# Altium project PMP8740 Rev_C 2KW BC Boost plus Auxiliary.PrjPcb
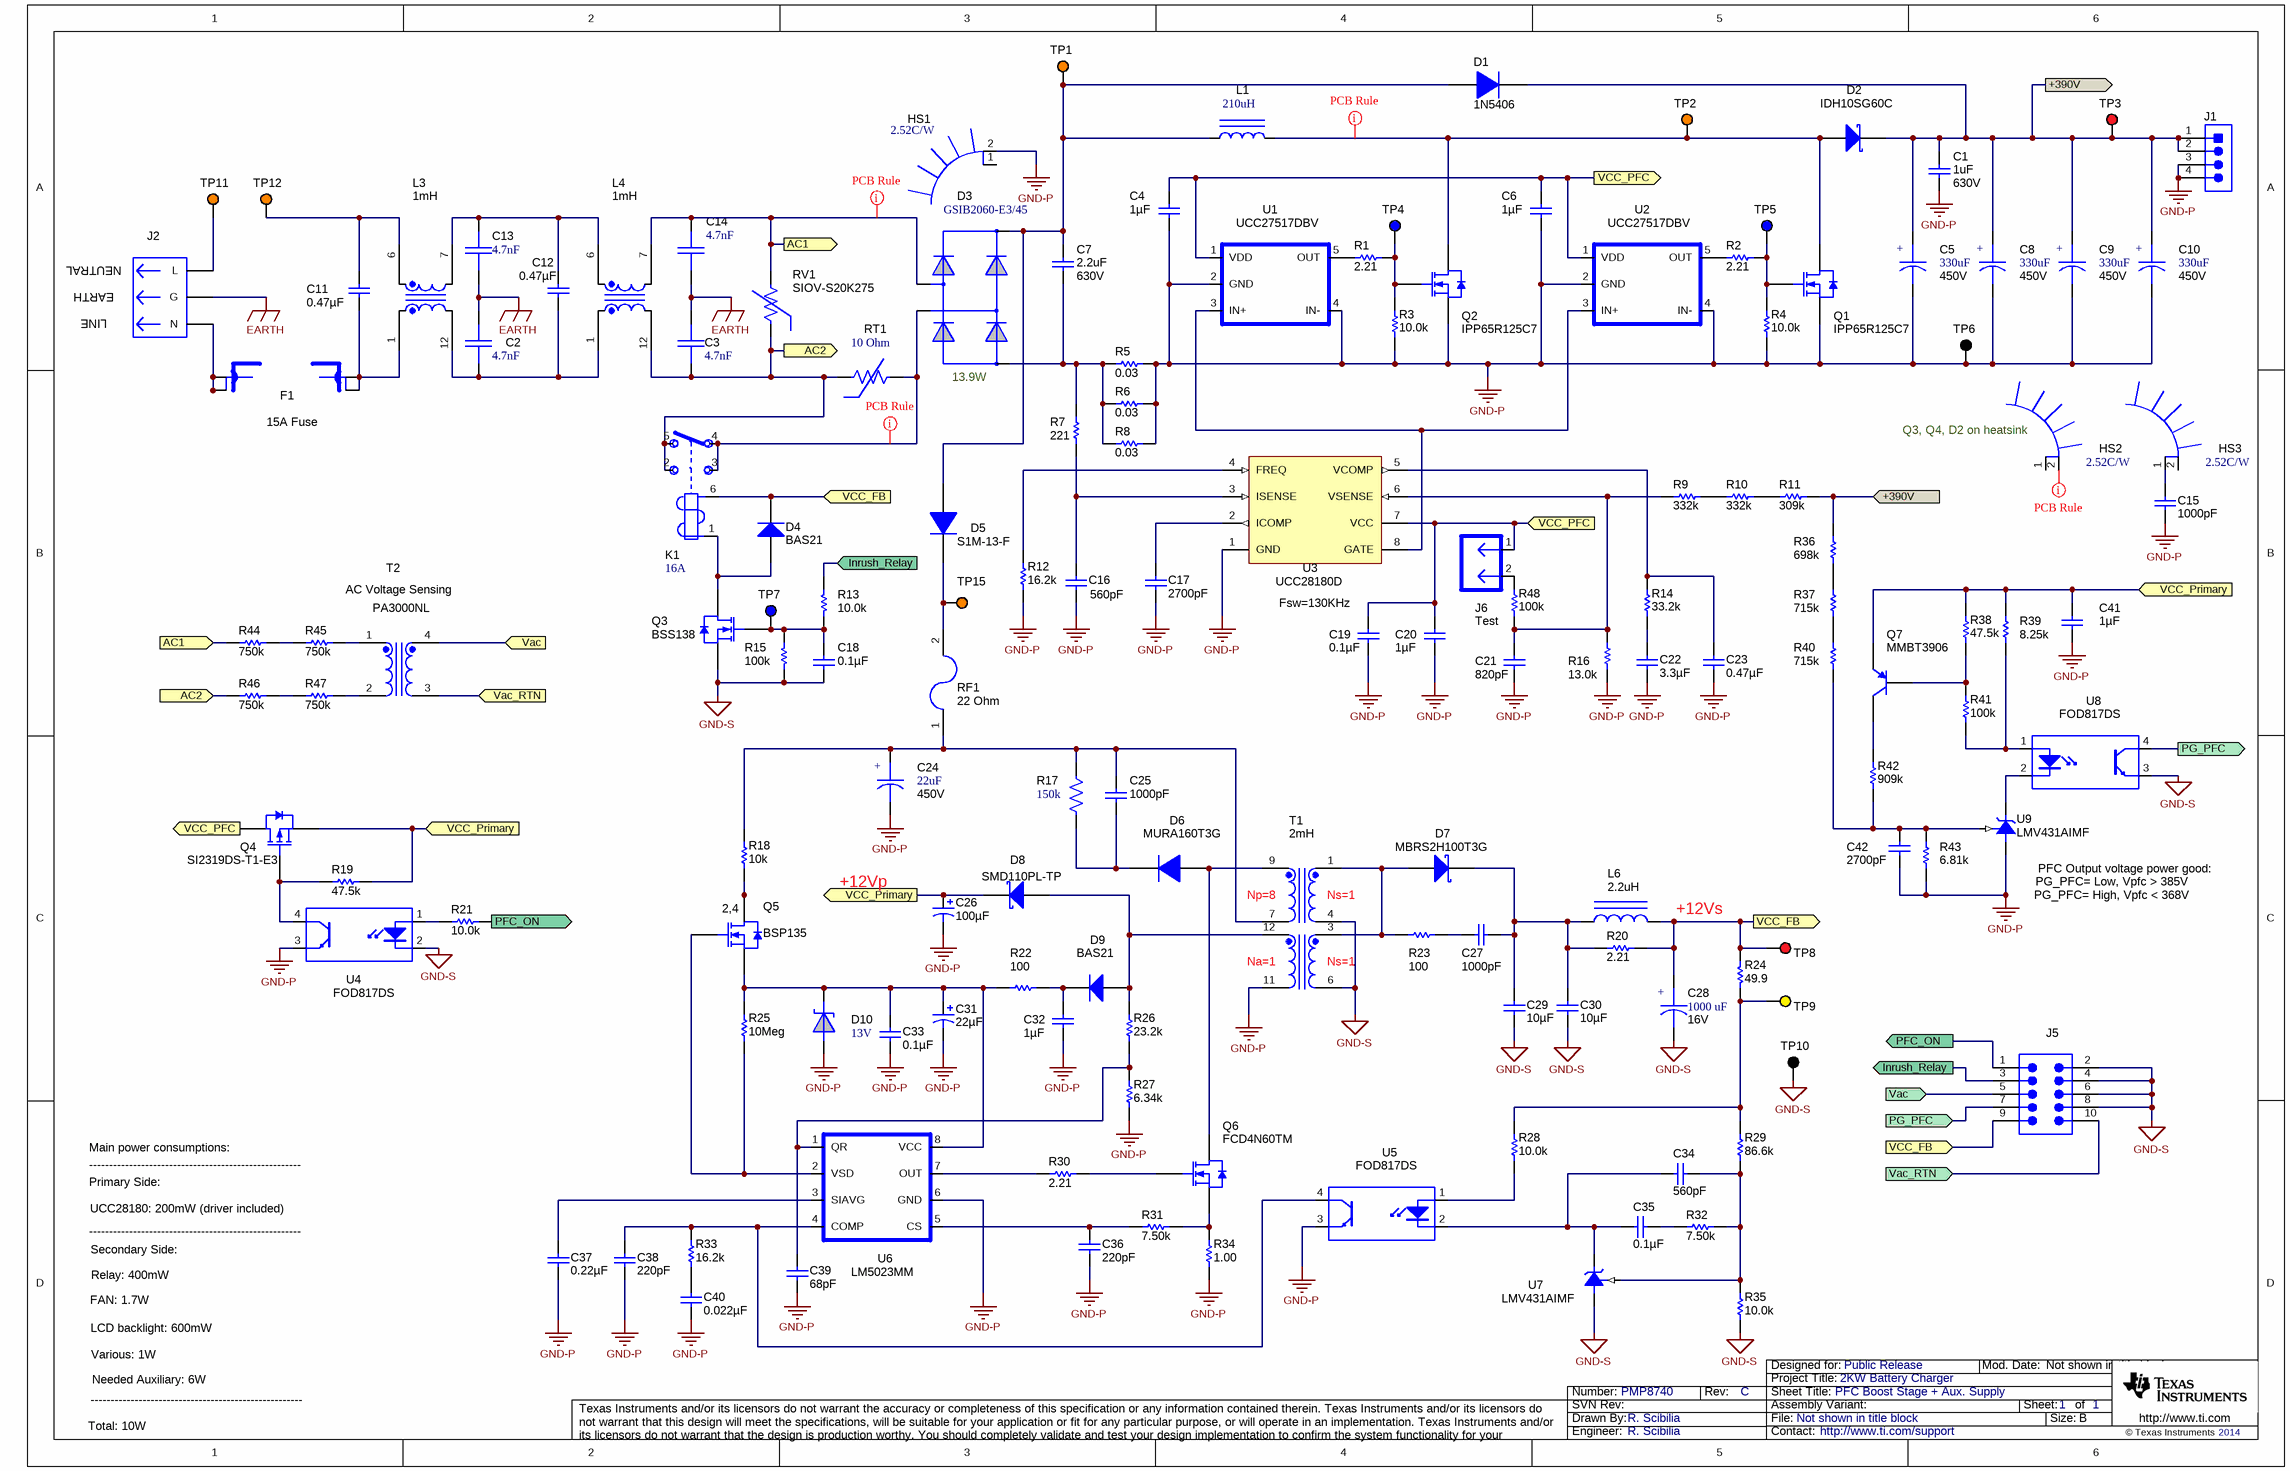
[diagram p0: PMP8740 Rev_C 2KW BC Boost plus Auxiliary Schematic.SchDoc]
CopyrightYear: 2014; PCB_Layout: R. Scibilia; PCB_Rev: C; PRJ_Customer: Public Release; PRJ_Engineer: R. Scibilia; PRJ_Number: PMP8740; PRJ_Title: 2KW Battery Charger; SCH_Rev: C; TechSupport: http://www.ti.com/support
1 sheet, 147 parts. Net scope: flat (ports and power ports of the same name join across sheets).
Board file: PMP8740 Rev_C 2KW BC Boost plus Auxiliary Board.PcbDoc

## Sheet PMP8740 Rev_C 2KW BC Boost plus Auxiliary Schematic.SchDoc: PFC Boost Stage + Aux. Supply
size 431 x 279 mm; Date: Not shown in title block; ApprovedBy: Not shown in title block; CheckedBy: Not shown in title block; Author: Not shown in title block; CompanyName: Not shown in title block; DrawnBy: R. Scibilia; Engineer: Not shown in title block; Organization: Not shown in title block; Address1: Not shown in title block; Address2: Not shown in title block; Address3: Not shown in title block; Address4: Not shown in title block; DocumentNumber: 1; Revision: Use project parameter SCH_Rev; SheetNumber: 1; SheetTotal: 1; PageSetup: Record=PageOptions|CenterHorizontal=True|CenterVertical=True|PrintScale=1.00|XCorrection=1.00|YCorrection=1.00|PrintKind=0|BorderSize=5000000|LeftOffset=0|BottomOffset=0|Orientation=2|PaperLength=1000|PaperWidth=1000|Scale=100|PaperSource=15|PrintQuality=600|MediaType=1|DitherType=10|PaperKind=Letter|PrintScaleMode=1

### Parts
C1  value 1uF  VDC_V: 630V  [B32924_21.5mm]  (hidden comment: R75PR4100AA30K)
C2  value 4.7nF  [CAP_LEAD_394]  (hidden comment: C961U472MYWDBA7317)
C3  value 4.7nF  [CAP_LEAD_394]  (hidden comment: C961U472MYWDBA7317)
C4  ValueDisplayed: 1µF  [0603]  (hidden comment: C1608X7R1E105K080AB)
C5  value 330uF  Voltage: 450V  [CAP_381L_35MM]  (hidden comment: EET-ED2W331EA)
C6  ValueDisplayed: 1µF  [0603]  (hidden comment: C1608X7R1E105K080AB)
C7  value 2.2uF  Value2: 630V  [B32923_29.5mm]  (hidden comment: ECW-FA2J225J)
C8  value 330uF  Voltage: 450V  [CAP_381L_35MM]  (hidden comment: EET-ED2W331EA)
C9  value 330uF  Voltage: 450V  [CAP_381L_35MM]  (hidden comment: EET-ED2W331EA)
C10  value 330uF  Voltage: 450V  [CAP_381L_35MM]  (hidden comment: EET-ED2W331EA)
C11  ValueDisplayed: 0.47µF  [CAPRR2250W80L2550T850H1750]  (hidden comment: ECQ-U2A474ML)
C12  ValueDisplayed: 0.47µF  [CAPRR2250W80L2550T850H1750]  (hidden comment: ECQ-U2A474ML)
C13  value 4.7nF  [CAP_LEAD_394]  (hidden comment: C961U472MYWDBA7317)
C14  value 4.7nF  [CAP_LEAD_394]  (hidden comment: C961U472MYWDBA7317)
C15  ValueDisplayed: 1000pF  [1206]  (hidden comment: CC1206KKX7RCBB102)
C16  ValueDisplayed: 560pF  [0603]  (hidden comment: C1608C0G1H561J)
C17  ValueDisplayed: 2700pF  [0603]  (hidden comment: C1608C0G1H272J)
C18  ValueDisplayed: 0.1µF  [0603]  (hidden comment: C1608X7R1H104K)
C19  ValueDisplayed: 0.1µF  [0603]  (hidden comment: C1608X7R1H104K)
C20  ValueDisplayed: 1µF  [0603]  (hidden comment: C1608X7R1E105K080AB)
C21  ValueDisplayed: 820pF  [0603]  (hidden comment: C1608C0G1H821J)
C22  ValueDisplayed: 3.3µF  [1206]  (hidden comment: GRM31CR71C335KA01L)
C23  ValueDisplayed: 0.47µF  [0603]  (hidden comment: C1608X5R1A474K)
C24  value 22uF  Voltage: 450V  [CAP_ZL-7.5X14.5MM]  (hidden comment: EKXG451ELL220ML20S)
C25  ValueDisplayed: 1000pF  [0805_HV]  (hidden comment: C2012X7R2E102K)
C26  ValueDisplayed: 100µF  [SM_RADIAL_E]  (hidden comment: EEE-FK1E101P)
C27  ValueDisplayed: 1000pF  [0805_HV]  (hidden comment: C2012X7R2E102K)
C28  value 1000 uF  Voltage: 16V  [CAP_ALUM-10MM]  (hidden comment: UHM1C102MPD)
C29  ValueDisplayed: 10µF  [1210]  (hidden comment: C3225X7R1E106M)
C30  ValueDisplayed: 10µF  [1210]  (hidden comment: C3225X7R1E106M)
C31  ValueDisplayed: 22µF  [SM_RADIAL_D]  (hidden comment: EEE-FK1H220P)
C32  ValueDisplayed: 1µF  [0603]  (hidden comment: C1608X7R1E105K080AB)
C33  ValueDisplayed: 0.1µF  [0603]  (hidden comment: C1608X7R1H104K)
C34  ValueDisplayed: 560pF  [0603]  (hidden comment: C1608C0G1H561J)
C35  ValueDisplayed: 0.1µF  [0603]  (hidden comment: C1608X7R1H104K)
C36  ValueDisplayed: 220pF  [0603]  (hidden comment: C1608C0G1H221J)
C37  ValueDisplayed: 0.22µF  [0603]  (hidden comment: C1608X7R1C224K)
C38  ValueDisplayed: 220pF  [0603]  (hidden comment: C1608C0G1H221J)
C39  ValueDisplayed: 68pF  [0603]  (hidden comment: C1608C0G1H680J)
C40  ValueDisplayed: 0.022µF  [0603]  (hidden comment: C1608X7R2A223K)
C41  ValueDisplayed: 1µF  [0603]  (hidden comment: C1608X7R1E105K080AB)
C42  ValueDisplayed: 2700pF  [0603]  (hidden comment: C1608C0G1H272J)
D1  1N5406  [DO-201AD]
D2  IDH10SG60C  [TO-220-2]
D3  value GSIB2060-E3/45  [BRIDGE-TSIL_PKG]  (hidden comment: D-BRIDGE_GSIB_20A_SERIES)
D4  value BAS21  [SOT-23]  (hidden comment: BAS21-7-F)
D5  S1M-13-F  [SMA]
D6  MURA160T3G  [SMA]
D7  MBRS2H100T3G  [SMB]
D8  SMD110PL-TP  [SOD-123FL]
D9  value BAS21  [SOT-23]  (hidden comment: BAS21-7-F)
D10  value 13V  [SOD-323]  (hidden comment: D-MMSZ52XXBS_SERIES)
F1  15A Fuse  [FUSE_HOLDER_1/4]
HS1  value 2.52C/W  [HEATSINK_780603B0200]  (hidden comment: HEATSINK_780603B0200)
HS2  value 2.52C/W  [HEATSINK_780603B0200]  (hidden comment: HEATSINK_780603B0200)
HS3  value 2.52C/W  [HEATSINK_780603B0200]  (hidden comment: HEATSINK_780603B0200)
J1  0015244557  [CONN_0015244557]  (value not drawn)
J2  703W-00/54  [CONN_QUALTEK-703W-0054]  (value not drawn)
J5  5103308-1  [CONN_5103308-1]  (value not drawn)
J6  Test  [HDR100_1X2]
K1  value 16A  [RELAY_ALZ_FORM_A]  (hidden comment: ALZ51B12)
L1  value 210uH  [IND_TOR_1600MIL]  (hidden comment: 170.804 (SDR 15,0-0,21))
L3  value 1mH  [WE-CMB_XL]  (hidden comment: 744825510)
L4  value 1mH  [WE-CMB_XL]  (hidden comment: 744825510)
L6  value 2.2uH  [WE-PD2-MS]  (hidden comment: 7447745022)
Q1  IPP65R125C7  [TO-220AB]
Q2  IPP65R125C7  [TO-220AB]
Q3  BSS138  [SOT-23]
Q4  SI2319DS-T1-E3  [SOT-23]
Q5  BSP135  [SOT-223]
Q6  FCD4N60TM  [DPAK]
Q7  MMBT3906  [SOT-23]
R1  value 2.21  [0805_HV]  (hidden comment: CRCW08052R21FKEA)
R2  value 2.21  [0805_HV]  (hidden comment: CRCW08052R21FKEA)
R3  value 10.0k  [0603]  (hidden comment: CRCW060310K0FKEA)
R4  value 10.0k  [0603]  (hidden comment: CRCW060310K0FKEA)
R5  value 0.03  [2512]  (hidden comment: CSRN2512FK30L0)
R6  value 0.03  [2512]  (hidden comment: CSRN2512FK30L0)
R7  value 221  [0603]  (hidden comment: CRCW0603221RFKEA)
R8  value 0.03  [2512]  (hidden comment: CSRN2512FK30L0)
R9  value 332k  [1206]  (hidden comment: CRCW1206332KFKEA)
R10  value 332k  [1206]  (hidden comment: CRCW1206332KFKEA)
R11  value 309k  [1206]  (hidden comment: CRCW1206309KFKEA)
R12  value 16.2k  [0603]  (hidden comment: CRCW060316K2FKEA)
R13  value 10.0k  [0603]  (hidden comment: CRCW060310K0FKEA)
R14  value 33.2k  [0603]  (hidden comment: CRCW060333K2FKEA)
R15  value 100k  [0603]  (hidden comment: CRCW0603100KFKEA)
R16  value 13.0k  [0603]  (hidden comment: CRCW060313K0FKEA)
R17  value 150k  [R2010]  (hidden comment: STD)
R18  value 10k  [2512M]  (hidden comment: CRCW251210K0FKEGHP)
R19  value 47.5k  [0603]  (hidden comment: CRCW060347K5FKEA)
R20  value 2.21  [0805_HV]  (hidden comment: CRCW08052R21FKEA)
R21  value 10.0k  [0603]  (hidden comment: CRCW060310K0FKEA)
R22  value 100  [1206]  (hidden comment: CRCW1206100RFKEA)
R23  value 100  [1206]  (hidden comment: CRCW1206100RFKEA)
R24  value 49.9  [0603]  (hidden comment: CRCW060349R9FKEA)
R25  value 10Meg  [1206]  (hidden comment: CRCW120610M0JNEA)
R26  value 23.2k  [0603]  (hidden comment: CRCW060323K2FKEA)
R27  value 6.34k  [0603]  (hidden comment: CRCW06036K34FKEA)
R28  value 10.0k  [0603]  (hidden comment: CRCW060310K0FKEA)
R29  value 86.6k  [0603]  (hidden comment: CRCW060386K6FKEA)
R30  value 2.21  [0805_HV]  (hidden comment: CRCW08052R21FKEA)
R31  value 7.50k  [0603]  (hidden comment: CRCW06037K50FKEA)
R32  value 7.50k  [0603]  (hidden comment: CRCW06037K50FKEA)
R33  value 16.2k  [0603]  (hidden comment: CRCW060316K2FKEA)
R34  value 1.00  [1206]  (hidden comment: CRCW12061R00FKEA)
R35  value 10.0k  [0603]  (hidden comment: CRCW060310K0FKEA)
R36  value 698k  [1206]  (hidden comment: CRCW1206698KFKEA)
R37  value 715k  [1206]  (hidden comment: CRCW1206715KFKEA)
R38  value 47.5k  [0603]  (hidden comment: CRCW060347K5FKEA)
R39  value 8.25k  [0603]  (hidden comment: CRCW06038K25FKEA)
R40  value 715k  [1206]  (hidden comment: CRCW1206715KFKEA)
R41  value 100k  [0603]  (hidden comment: CRCW0603100KFKEA)
R42  value 909k  [0603]  (hidden comment: CRCW0603909KFKEA)
R43  value 6.81k  [0603]  (hidden comment: CRCW06036K81FKEA)
R44  value 750k  [1206]  (hidden comment: CRCW1206750KFKEA)
R45  value 750k  [1206]  (hidden comment: CRCW1206750KFKEA)
R46  value 750k  [1206]  (hidden comment: CRCW1206750KFKEA)
R47  value 750k  [1206]  (hidden comment: CRCW1206750KFKEA)
R48  value 100k  [0603]  (hidden comment: CRCW0603100KFKEA)
RF1  value 22 Ohm  [EMC2]  (hidden comment: EMC2-22RKI)
RT1  value 10 Ohm  [DISK-7X21MM]  (hidden comment: B57464S100M)
RV1  SIOV-S20K275  [DISK-846]
T1  value 2mH  [Wurth_760871113]  (hidden comment: TBD)
T2  PA3000NL  [PULSE_PA3000NL]
TP1  5008  [Keystone5008]  (value not drawn)
TP2  5008  [Keystone5008]  (value not drawn)
TP3  5005  [Keystone5005]  (value not drawn)
TP4  5122  [Keystone5122]  (value not drawn)
TP5  5122  [Keystone5122]  (value not drawn)
TP6  5006  [Keystone5006]  (value not drawn)
TP7  5122  [Keystone5122]  (value not drawn)
TP8  5000  [Keystone5000]  (value not drawn)
TP9  5004  [Keystone5004]  (value not drawn)
TP10  5001  [Keystone5001]  (value not drawn)
TP11  5008  [Keystone5008]  (value not drawn)
TP12  5008  [Keystone5008]  (value not drawn)
TP15  5008  [Keystone5008]  (value not drawn)
U1  UCC27517DBV  [SOT23-5P]
U2  UCC27517DBV  [SOT23-5P]
U3  UCC28180D  [D0008A_N]
U4  FOD817DS  [N04C]
U5  FOD817DS  [N04C]
U6  LM5023MM  [DGK8]
U7  LMV431AIMF  [MF03A_N]
U8  FOD817DS  [N04C]
U9  LMV431AIMF  [MF03A_N]

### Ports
+390V, AC1, AC2, Inrush_Relay, PFC_ON, PG_PFC, Vac, Vac_RTN, VCC_FB, VCC_PFC, VCC_Primary

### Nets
EARTH: C2.1 C3.1 C13.2 C14.2 J2.3(G)
GND-P: C1.2 C4.2 C5.2 C6.2 C8.2 C9.2 C10.2 C15.2 C16.2 C17.2 C19.2 C20.2 C21.2 C22.2 C23.2 C24.2 C26.2(-) C31.2(-) C32.2 C33.1 C36.2 C37.2 C38.2 C39.2 C40.2 C41.2 C42.2 D10.2(A) HS1.2 J1.3 J1.4 Q1.3(S) Q2.3(S) R3.1 R4.1 R5.2 R6.2 R8.2 R12.1 R16.1 R27.1 R34.1 R43.1 T1.11 TP6.1 U1.2(GND) U1.4(IN-) U2.2(GND) U2.4(IN-) U3.1(GND) U4.3(E) U5.3(E) U6.6(GND) U9.3(A)
GND-S: C18.1 C28.2 C29.2 C30.2 J5.2 J5.4 J5.6 J5.8 Q3.2(S) R15.1 R35.2 T1.4 T1.6 TP10.1 U4.2(K) U7.3(A) U8.3(E)
+390V: C1.1 C5.1 C8.1 C9.1 C10.1 D1.1(K) D2.1(K) J1.1 J1.2 R11.2 R36.2 TP3.1 ; port +390V
AC1: C14.1 D3.2(AC) L4.7 R44.2 RV1.2 ; port AC1
AC2: C3.2 K1.2 K1.5 L4.12 R46.2 RT1.1 RV1.1 ; port AC2
Inrush_Relay: J5.3 R13.2 ; port Inrush_Relay
PFC_ON: J5.1 R21.1 ; port PFC_ON
PG_PFC: J5.7 U8.4(C) ; port PG_PFC
Vac: J5.5 T2.4 ; port Vac
Vac_RTN: J5.10 T2.3 ; port Vac_RTN
VCC_FB: C28.1 D4.3(K) J5.9 K1.6 L6.2 R20.2 R24.1 TP8.1 ; port VCC_FB
VCC_PFC: C4.1 C6.1 C19.1 C20.1 J6.1 Q4.3(D) U1.1(VDD) U2.1(VDD) U3.7(VCC) ; port VCC_PFC
VCC_Primary: C26.1(+) C41.1 D8.1(K) Q4.2(S) Q7.2(E) R19.2 R38.2 R39.2 ; port VCC_Primary
NetC2_2: C2.2 C12.1 L3.12 L4.1
NetC7_1: C7.1 D1.2(A) D3.1(+) D5.2(A) L1.1 TP1.1
NetC7_2: C7.2 D3.4(-) R5.1 R6.1 R7.2 R8.1
NetC11_1: C11.1 F1.3 F1.4 L3.1
NetC11_2: C11.2 L3.6 TP12.1
NetC12_2: C12.2 C13.1 L3.7 L4.6
NetC15_1: C15.1 HS3.1
NetC16_1: C16.1 R7.1 U3.3(ISENSE)
NetC17_1: C17.1 U3.2(ICOMP)
NetC18_2: C18.2 Q3.1(G) R13.1 R15.2 TP7.1
NetC21_1: C21.1 R9.2 R16.2 R48.2 U3.6(VSENSE)
NetC22_1: C22.1 R14.1
NetC23_1: C23.1 R14.2 U3.5(VCOMP)
NetC24_1: C24.1 C25.1 R17.1 R18.2 RF1.1 T1.7
NetC25_2: C25.2 D6.1(K) R17.2
NetC27_1: C27.1 R23.2
NetC27_2: C27.2 C29.1 C30.1 D7.1(K) L6.1 R20.1
NetC31_1: C31.1(+) C33.2 D10.1(C) Q5.3(S) R22.1 R25.2 U6.8(VCC)
NetC32_1: C32.1 D9.3(K) R22.2
NetC34_1: C34.1 C35.1 U5.2(K) U7.2(K)
NetC34_2: C34.2 R29.1 R32.2 R35.1 U7.1(REF)
NetC35_2: C35.2 R32.1
NetC36_1: C36.1 R31.1 U6.5(CS)
NetC37_1: C37.1 U6.3(SIAVG)
NetC38_1: C38.1 R33.2 U5.4(C) U6.4(COMP)
NetC39_1: C39.1 R26.1 R27.2 U6.1(QR)
NetC40_1: C40.1 R33.1
NetC42_1: C42.1 R40.1 R42.1 R43.2 U9.1(REF)
NetD2_2: D2.2(A) L1.2 Q1.2(D) Q2.2(D) TP2.1
NetD3_3: D3.3(AC) K1.3 K1.4 RT1.2
NetD4_1: D4.1(A) K1.1 Q3.3(D)
NetD5_1: D5.1(K) RF1.2 TP15.1
NetD6_2: D6.2(A) Q6.4(D) T1.9
NetD7_2: D7.2(A) R23.1 T1.1 T1.3
NetD8_2: D8.2(A) D9.1(A) R26.2 T1.12
NetF1_1: F1.1 F1.2 J2.2(N)
NetJ2_1: J2.1(L) TP11.1
NetJ6_2: J6.2 R48.1
NetQ1_1: Q1.1(G) R2.2 R4.2 TP5.1
NetQ2_1: Q2.1(G) R1.2 R3.2 TP4.1
NetQ4_1: Q4.1(G) R19.1 U4.4(C)
NetQ5_1: Q5.1(G) R25.1 U6.2(VSD)
NetQ5_2: Q5.2(D) Q5.4(D) R18.1
NetQ6_1: Q6.1(G) R30.2
NetQ6_3: Q6.3(S) R31.2 R34.2
NetQ7_1: Q7.1(B) R38.1 R41.2
NetQ7_3: Q7.3(C) R42.2
NetR1_1: R1.1 U1.5(OUT)
NetR2_1: R2.1 U2.5(OUT)
NetR9_1: R9.1 R10.2
NetR10_1: R10.1 R11.1
NetR12_2: R12.2 U3.4(FREQ)
NetR21_2: R21.2 U4.1(A)
NetR24_2: R24.2 R28.2 R29.2 TP9.1
NetR28_1: R28.1 U5.1(A)
NetR30_1: R30.1 U6.7(OUT)
NetR36_1: R36.1 R37.2
NetR37_1: R37.1 R40.2
NetR39_1: R39.1 R41.1 U8.1(A)
NetR44_1: R44.1 R45.2
NetR45_1: R45.1 T2.1
NetR46_1: R46.1 R47.2
NetR47_1: R47.1 T2.2
NetU1_3: U1.3(IN+) U2.3(IN+) U3.8(GATE)
NetU8_2: U8.2(K) U9.2(K)

Not connected (* = marked no-connect by the designer): HS1 1; HS2 1 2; HS3 2

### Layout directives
rule Clearance Constraint [Clearance = 30mil]: AC1, NetD2_2, NetD3_3, NetHS2_2

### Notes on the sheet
- NEUTRAL
- EARTH
- LINE
- (near D3) 13.9W
- (near HS2) Q3, Q4, D2 on heatsink
- AC Voltage Sensing
- Fsw=130KHz
- +12Vp
- (near T1) Np=8
- (near T1) Ns=1
- (near U9) PG_PFC= Low, Vpfc > 385V
- PG_PFC= High, Vpfc < 368V
- (near U9) PFC Output voltage power good:
- (near T1) Na=1
- +12Vs
- Main power consumptions:
- -----------------------------------------------------
- Primary Side:
- UCC28180: 200mW (driver included)
- Relay: 400mW
- Secondary Side:
- FAN: 1.7W
- Various: 1W
- LCD backlight: 600mW
- Total: 10W
- Needed Auxiliary: 6W

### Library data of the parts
C1 = B32924C3155M: CAP, Polypropilene, 1uF, 630V, +/-20%, TH; Manufacturer: Kemet; Polarized: N; CompType: Capacitor; ValueDisplayed: 1µF; U/M: EA; Cap_F: 0.0000015; Tolerance_%: 20; Value1: 0.017 ohm; ESR_Ohm: 0.017; IRMS_A: 0.146; TaMax_C: 110
C2 C3 C13 C14 = CAP_ECKANA_10MM: Capacitor, Ceramic Disk X1Y2, 250Vac; Manufacturer: Kemet; Area: 128
C4 C6 C20 C32 C41 = C1608X7R1E105K080AB: CAP, CERM, 1uF, 25V, +/-10%, X7R, 0603; Manufacturer: TDK; Polarized: N; CompType: Capacitor; U/M: EA; Cap_F: 0.000001; Tolerance_%: 10; Value1: Unknown; VDC_V: 25; TaMin_C: -55; TaMax_C: 125
C5 C8-C10 = CAP_381L_35MM: Capacitor, Electrolytic, Snap in., 330uF, 450Vdc, 105C, 20%; Manufacturer: Panasonic; Area: 1,561,450
C7 = B32923C3225M: CAP, Film Polyprop., 2.2uF, 630Vdc, 6Arms @ 200KHz, 20%, TH; Manufacturer: Panasonic; Polarized: N; CompType: Capacitor; ValueDisplayed: 2.2µF; U/M: EA; Cap_F: 0.0000022; Tolerance_%: 20; Value1: Unknown; VDC_V: 630; TaMax_C: 110
C11 C12 = ECQ-U2A474ML: CAP, Film, 0.47uF, 275V, +/-20%, TH; Manufacturer: Panasonic; Polarized: N; CompType: Capacitor; U/M: EA; Cap_F: 0.00000047; Tolerance_%: 20; Value1: Unknown; VDC_V: 275; TaMin_C: -40; TaMax_C: 100; Cap_Case: Radial 25x8.5x18.5
C15 = CC1206KKX7RCBB102: CAP, CERM, 1000pF, 1000V, +/-10%, X7R, 1206; Manufacturer: Yageo America; Polarized: N; CompType: Capacitor; U/M: EA; Cap_F: 0.000000001; Tolerance_%: 10; Value1: Unknown; VDC_V: 1000; TaMin_C: -55; TaMax_C: 125
C16 C34 = C1608C0G1H561J: CAP, CERM, 560pF, 50V, +/-5%, C0G/NP0, 0603; Manufacturer: TDK; Polarized: N; CompType: Capacitor; U/M: EA; Cap_F: 0.00000000056; Tolerance_%: 5; ESR_Ohm: 0.0858; Value1: 0.0858 ohm; VDC_V: 50; TaMin_C: -55; TaMax_C: 125
C17 C42 = C1608C0G1H272J: CAP, CERM, 2700pF, 50V, +/-5%, C0G/NP0, 0603; Manufacturer: TDK; Polarized: N; CompType: Capacitor; U/M: EA; Cap_F: 0.0000000027; Tolerance_%: 5; Value1: Unknown; VDC_V: 50; TaMin_C: -55; TaMax_C: 125
C18 C19 C33 C35 = C1608X7R1H104K: CAP, CERM, 0.1uF, 50V, +/-10%, X7R, 0603; Manufacturer: TDK; Polarized: N; CompType: Capacitor; U/M: EA; Cap_F: 0.0000001; Tolerance_%: 10; ESR_Ohm: 0.017; Value1: 0.017 ohm; VDC_V: 50; TaMin_C: -55; TaMax_C: 125
C21 = C1608C0G1H821J: CAP, CERM, 820pF, 50V, +/-5%, C0G/NP0, 0603; Manufacturer: TDK; Polarized: N; CompType: Capacitor; U/M: EA; Cap_F: 0.00000000082; Tolerance_%: 5; ESR_Ohm: 0.0482; Value1: 0.0482 ohm; VDC_V: 50; TaMin_C: -55; TaMax_C: 125
C22 = GRM31CR71C335KA01L: CAP, CERM, 3.3uF, 16V, +/-10%, X7R, 1206; Manufacturer: MuRata; Polarized: N; CompType: Capacitor; U/M: EA; Cap_F: 0.0000033; Tolerance_%: 10; Value1: Unknown; VDC_V: 16; TaMin_C: -55; TaMax_C: 125
C23 = C1608X5R1A474K: CAP, CERM, 0.47uF, 10V, +/-10%, X5R, 0603; Manufacturer: TDK; Polarized: N; CompType: Capacitor; U/M: EA; Cap_F: 0.00000047; Tolerance_%: 10; ESR_Ohm: 0.0101; Value1: 0.0101 ohm; TaMin_C: -55; TaMax_C: 85
C24 = CAP_ZL_16MM_SERIES: Capacitor, Electrolytic, 105C, 20%; Manufacturer: Nippon Chemi-Con; Area: 283,687
C25 C27 = C2012X7R2E102K: CAP, CERM, 1000pF, 250V, +/-10%, X7R, 0805; Manufacturer: TDK; Polarized: N; CompType: Capacitor; U/M: EA; Cap_F: 0.000000001; Tolerance_%: 10; ESR_Ohm: 0.2815; Value1: 0.2815 ohm; VDC_V: 250; TaMin_C: -55; TaMax_C: 125; Cap_Case: 0805
C26 = EEE-FK1E101P: CAP, AL, 100uF, 25V, +/-20%, 0.26 ohm, SMD; Manufacturer: Panasonic; Polarized: Y; CompType: Capacitor; U/M: EA; Cap_F: 0.0001; Tolerance_%: 20; VDC_V: 25; ESR_Ohm: 0.26; IRMS_A: 0.3; TaMin_C: -55; TaMax_C: 105; Cap_Case: E
C28 = CAP_EKZE_10MM_SERIES: Capacitor, Alum Electrolytic 16 V, 105C, ±20%; Manufacturer: Nichicon; Area: 96.42 mm
C29 C30 = C3225X7R1E106M: CAP, CERM, 10uF, 25V, +/-20%, X7R, 1210; Manufacturer: TDK; Polarized: N; CompType: Capacitor; U/M: EA; Cap_F: 0.00001; Tolerance_%: 20; ESR_Ohm: 0.0027; Value1: 0.0027 ohm; VDC_V: 25; IRMS_A: 3; TaMin_C: -55; TaMax_C: 125
C31 = EEE-FK1H220P: CAP, AL, 22uF, 50V, +/-20%, 0.88 ohm, SMD; Manufacturer: Panasonic; Polarized: Y; CompType: Capacitor; U/M: EA; Cap_F: 0.000022; Tolerance_%: 20; VDC_V: 50; ESR_Ohm: 0.88; IRMS_A: 0.165; TaMin_C: -55; TaMax_C: 105; Cap_Case: D
C36 C38 = C1608C0G1H221J: CAP, CERM, 220pF, 50V, +/-5%, C0G/NP0, 0603; Manufacturer: TDK; Polarized: N; CompType: Capacitor; U/M: EA; Cap_F: 0.00000000022; Tolerance_%: 5; ESR_Ohm: 0.0831; Value1: 0.0831 ohm; VDC_V: 50; TaMin_C: -55; TaMax_C: 125
C37 = C1608X7R1C224K: CAP, CERM, 0.22uF, 16V, +/-10%, X7R, 0603; Manufacturer: TDK; Polarized: N; CompType: Capacitor; U/M: EA; Cap_F: 0.00000022; Tolerance_%: 10; ESR_Ohm: 0.0125; Value1: 0.0125 ohm; VDC_V: 16; TaMin_C: -55; TaMax_C: 125
C39 = C1608C0G1H680J: CAP, CERM, 68pF, 50V, +/-5%, C0G/NP0, 0603; Manufacturer: TDK; Polarized: N; CompType: Capacitor; U/M: EA; Cap_F: 0.000000000068; Tolerance_%: 5; ESR_Ohm: 0.1724; Value1: 0.1724 ohm; VDC_V: 50; TaMin_C: -55; TaMax_C: 125
C40 = C1608X7R2A223K: CAP, CERM, 0.022uF, 100V, +/-10%, X7R, 0603; Manufacturer: TDK; Polarized: N; CompType: Capacitor; U/M: EA; Cap_F: 0.000000022; Tolerance_%: 10; ESR_Ohm: 0.037; Value1: 0.037 ohm; VDC_V: 100; TaMin_C: -55; TaMax_C: 125
D1 = 1N5406: Diode, Switching-Bridge, 600V, 3A, TH; Manufacturer: Vishay-Semiconductor; U/M: EA; Vf_V: 1.2; Value2: 1.2V; Io_A: 3; Vr_V: 600; TJmax_C: 150
D2 = C3D08060A: Diode, Schottky, 600V, 10A, TH; Manufacturer: Infineon; U/M: EA; Vf_V: 1.8; Value2: 1.8V; Io_A: 8; Vr_V: 600; TJmax_C: 175; RJC_CperW: 1.5
D3 = D-BRIDGE_GSIB_20A_SERIES: Diode, Single-Phase In-Line Bridge Rectifier, 20A, 600V; Manufacturer: Vishay; Area: 266640; Description: Diode, Single-Phase In-Line Bridge Rectifier, 20A, xxxV
D4 D9 = BAS21-7-F: Diode, Switching, 200V, 0.2A, SOT-23; Manufacturer: Diodes Inc.; U/M: EA; Vf_V: 1.25; Value2: 1.25V; Io_A: 0.2; Vr_V: 200; TJmax_C: 150; RJC_CperW: 500
D5 = US1M-13-F: Diode, Standard, 1000V, 1A, SMA; Manufacturer: Diodes Inc.; U/M: EA; Vf_V: 1.7; Value2: 1.7V; Io_A: 1; Vr_V: 1000; TJmax_C: 150; RJC_CperW: 30
D6 = MURA160T3G: Diode, Ultrafast, 600V, 1A, SMA; Manufacturer: ON Semiconductor; U/M: EA; Vf_V: 1.05; Value2: 1.05V; Io_A: 1; Vr_V: 600; TJmax_C: 175
D7 = MBRS260T3G: Diode, Schottky, 100V, 2A, SMB; Manufacturer: ON Semiconductor; U/M: EA; Vf_V: 0.63; Value2: 0.63V; Io_A: 2; TJmax_C: 125; RJC_CperW: 24
D8 = MBR1H100SFT3G: Diode, Schottky, 100V, 1A, SOD-123FL; Manufacturer: Micro Commercial; U/M: EA; Vf_V: 0.76; Value2: 0.76V; Io_A: 1; Vr_V: 100; TJmax_C: 175; RJC_CperW: 85
D10 = D-MMSZ52XXBS_SERIES: Diode, Zener, 13V, 9.5-mA, 200mW; PartNumber: MMSZ5243BS-7-F; Manufacturer: Diodes; Area: 195000
F1 = FUSEHOLDER_1/4BM: Fuseholder, 1/4" fuses, board mount + 15A Fuse; Manufacturer: Littlefuse; PartNumber: 2 times 01020071Z + fuse 15A 0326015.HXP; area: 499200; Value: 01020071Z
HS1 = HEATSINK_780603B0200: Heatsink,  Vertical-mount; Manufacturer: Fischer; PartNumber: SK 481-50; area: 2480100
HS2 HS3 = HEATSINK_780603B0200: Heatsink,  Vertical-mount; Manufacturer: Fischer; PartNumber: SK 481-100; area: 2480100
J1 = 0015244557: Header, 4POS, 200mil, Vertical, Tin, TH; Manufacturer: Molex; SymbolCreator: a0412235; CompType: Connector; U/M: EA
J2 = 703W-00/54: AC Receptacle, 10A 250VAC; Manufacturer: Qualtek Electronics Corporation; SymbolCreator: a0799628; CompType: Connector; U/M: EA
J5 = 5103308-1: Header (shrouded), 100mil, 5x2, Gold, TH; Manufacturer: TE Connectivity; SymbolCreator: a0412235; CompType: Connector; U/M: EA
J6 = HEADER_1X2: Header, Male 2-pin, 100mil spacing,; Manufacturer: Sullins; PartNumber: PEC02SAAN; area: 20000; Value: PEC02SAAN
K1 = RELAY_ALZ_SERIES: Relay, SPST, 12V Coil Rating, Contact Rating 16A 250VAC; Manufacturer: Nais; Area: 424
L1 = IND_D-TOROID: Inductor, PFC Choke, 210uH 15A; Manufacturer: Kaschke; Area: 1,271,400
L3 L4 = 744825510: Coupled inductor, 1mH, 12A, 0.009 ohm, TH; Manufacturer: Wurth Elektronik eiSos; SymbolCreator: a0799628; ComponentName: 7448251201; Ind_H: 0.001; DCR_Ohm: 0.009; Isat: 5; U/M: EA
L6 = 7447745022: Inductor, Drum Core, Ferrite, 2.2uH, 3.5A, 0.03 ohm, SMD; Manufacturer: Wurth Elektronik eiSos; Ind_H: 2.2E-6; ValueDisplayed: 2.2µH; Imax_A: 3.5; Irms: 3.6A @ 40C rise; Isat: 3.5A @ 10% inductance drop; DCR_ohm: 0.03; U/M: EA
Q1 Q2 = IPP50R199CP: MOSFET, N-CH, 650V, 18A, TO-220AB; Manufacturer: Infineon Technologies; Alternate Manufacturer: None; U/M: EA; ChType: N; VdsMax_V: 650; Value1: 0.125 ohm; Rdson45_Ohm: 0; Value2: 35 nC; QgTyp_nC: 34; Vgs_V: 20; IdsMax_A: 17
Q3 = BSS138: MOSFET, N-CH, 50V, 0.22A, SOT-23; Manufacturer: Fairchild Semiconductor; Alternate Manufacturer: None; U/M: EA; ChType: N; VdsMax_V: 50; Value1: 6 ohm; Rdson45_Ohm: 6; Value2: 1.7 nC; QgTyp_nC: 1.7; Vgs_V: 20; IdsMax_A: 0.22
Q4 = SI2319DS-T1-E3: MOSFET, P-CH, -40V, -2.3A, SOT-23; Manufacturer: Vishay-Siliconix; Alternate Manufacturer: None; U/M: EA; ChType: P; VdsMax_V: -40; Value1: 0.13 ohm; Rdson45_Ohm: 0.13; Value2: 11.3 nC; QgTyp_nC: 11.3; Vgs_V: -20; IdsMax_A: -2.3
Q5 = ZXMN10A11G: MOSFET, N-CH, Depletion Mode, 600V, 20mA, SOT-223; Manufacturer: Diodes Inc.; Alternate Manufacturer: None; U/M: EA; ChType: N; Value1: 20 ohm; Value2: 5.4 nC; QgTyp_nC: 5.4; Vgs_V: 20; IdsMax_A: 1.9
Q6 = FCD4N60TM: MOSFET, N-CH, 600V, 3.9A, DPAK; Manufacturer: Fairchild Semiconductor; Alternate Manufacturer: None; U/M: EA; ChType: N; VdsMax_V: 600; Value1: 101 ohm; Rdson45_Ohm: 101; Value2: 12.8 nC; QgTyp_nC: 12.8; Vgs_V: 30; IdsMax_A: 3.9
Q7 = MMBT3906, Fairchild Semiconductor: Transistor, PNP, 40V, 0.2A, SOT-23; CompType: BJT; PNP: 1; NPN: 0; Vceo_V: 40; Vcesat1_V: 0.25; Value: 0.25V; IcRated_A: 0.2; HfeMax: 300; TaMin_C: -55; TaMax_C: 150; U/M: EA
R1 R2 R20 R30 = CRCW08052R21FKEA: RES, 2.21 ohm, 1%, 0.125W, 0805; Manufacturer: Vishay-Dale; CompType: Resistor; Value_Code: 2R21; Tolerance_%: 1; Power_W: 0.125; VDC_V: 150; TempCo: 100 ppm/C; EIA_Code: E96; U/M: EA
R3 R4 R13 R21 R28 R35 = CRCW060310K0FKEA: RES, 10.0k ohm, 1%, 0.1W, 0603; Manufacturer: Vishay-Dale; CompType: Resistor; Res_ohm: 10000; Value_Code: 10k0; Tolerance_%: 1; Power_W: 0.1; VDC_V: 75; TempCo: 100 ppm/C; EIA_Code: E96; U/M: EA
R5 R6 R8 = CSRN2512FK30L0: RES, 0.03 ohm, 1%, 2W, 2512; Manufacturer: Stackpole Electronics Inc; CompType: Resistor; Value_Code: R030; Tolerance_%: 1; Power_W: 2; TempCo: 200 ppm/C; EIA_Code: E96; U/M: EA
R7 = CRCW0603221RFKEA: RES, 221 ohm, 1%, 0.1W, 0603; Manufacturer: Vishay-Dale; CompType: Resistor; Value_Code: 221R; Tolerance_%: 1; Power_W: 0.1; VDC_V: 75; TempCo: 100 ppm/C; EIA_Code: E96; U/M: EA
R9 R10 = CRCW1206332KFKEA: RES, 332k ohm, 1%, 0.25W, 1206; Manufacturer: Vishay-Dale; CompType: Resistor; Res_ohm: 332000; Tolerance_%: 1; Power_W: 0.25; VDC_V: 200; TempCo: 100 ppm/C; EIA_Code: E96; U/M: EA
R11 = CRCW1206309KFKEA: RES, 309k ohm, 1%, 0.25W, 1206; Manufacturer: Vishay-Dale; CompType: Resistor; Res_ohm: 309000; Tolerance_%: 1; Power_W: 0.25; VDC_V: 200; TempCo: 100 ppm/C; EIA_Code: E96; U/M: EA
R12 R33 = CRCW060316K2FKEA: RES, 16.2k ohm, 1%, 0.1W, 0603; Manufacturer: Vishay-Dale; CompType: Resistor; Res_ohm: 16200; Value_Code: 16k2; Tolerance_%: 1; Power_W: 0.1; VDC_V: 75; TempCo: 100 ppm/C; EIA_Code: E96; U/M: EA
R14 = CRCW060333K2FKEA: RES, 33.2k ohm, 1%, 0.1W, 0603; Manufacturer: Vishay-Dale; CompType: Resistor; Res_ohm: 33200; Value_Code: 33k2; Tolerance_%: 1; Power_W: 0.1; VDC_V: 75; TempCo: 100 ppm/C; EIA_Code: E96; U/M: EA
R15 R41 R48 = CRCW0603100KFKEA: RES, 100k ohm, 1%, 0.1W, 0603; Manufacturer: Vishay-Dale; CompType: Resistor; Res_ohm: 100000; Tolerance_%: 1; Power_W: 0.1; VDC_V: 75; TempCo: 100 ppm/C; EIA_Code: E96; U/M: EA
R16 = CRCW060313K0FKEA: RES, 13.0k ohm, 1%, 0.1W, 0603; Manufacturer: Vishay-Dale; CompType: Resistor; Res_ohm: 13000; Value_Code: 13k0; Tolerance_%: 1; Power_W: 0.1; VDC_V: 75; TempCo: 100 ppm/C; EIA_Code: E96; U/M: EA
R17 = R2010_5%: Resistor, Chip, 0.6W, 1%; Area: 30800
R18 = CRCW25121K10JNEG: RES, 10.0k ohm, 1%, 1W, 2512; Manufacturer: Vishay-Dale; CompType: Resistor; Res_ohm: 1100; Tolerance_%: 5; Power_W: 1; VDC_V: 500; TempCo: 200 ppm/C; EIA_Code: E24; U/M: EA
R19 R38 = CRCW060347K5FKEA: RES, 47.5k ohm, 1%, 0.1W, 0603; Manufacturer: Vishay-Dale; CompType: Resistor; Res_ohm: 47500; Value_Code: 47k5; Tolerance_%: 1; Power_W: 0.1; VDC_V: 75; TempCo: 100 ppm/C; EIA_Code: E96; U/M: EA
R22 R23 = CRCW1206100RFKEA: RES, 100 ohm, 1%, 0.25W, 1206; Manufacturer: Vishay-Dale; CompType: Resistor; Value_Code: 100R; Tolerance_%: 1; Power_W: 0.25; VDC_V: 200; TempCo: 100 ppm/C; EIA_Code: E96; U/M: EA
R24 = CRCW060349R9FKEA: RES, 49.9 ohm, 1%, 0.1W, 0603; Manufacturer: Vishay-Dale; CompType: Resistor; Value_Code: 49R9; Tolerance_%: 1; Power_W: 0.1; VDC_V: 75; TempCo: 100 ppm/C; EIA_Code: E96; U/M: EA
R25 = CRCW120610M0JNEA: RES, 10Meg ohm, 5%, 0.25W, 1206; Manufacturer: Vishay-Dale; CompType: Resistor; Res_ohm: 10000000; Value_Code: 10M0; Tolerance_%: 5; Power_W: 0.25; VDC_V: 200; TempCo: 200 ppm/C; EIA_Code: E24; U/M: EA
R26 = CRCW060323K2FKEA: RES, 23.2k ohm, 1%, 0.1W, 0603; Manufacturer: Vishay-Dale; CompType: Resistor; Res_ohm: 23200; Value_Code: 23k2; Tolerance_%: 1; Power_W: 0.1; VDC_V: 75; TempCo: 100 ppm/C; EIA_Code: E96; U/M: EA
R27 = CRCW06036K34FKEA: RES, 6.34k ohm, 1%, 0.1W, 0603; Manufacturer: Vishay-Dale; CompType: Resistor; Res_ohm: 6340; Value_Code: 6k34; Tolerance_%: 1; Power_W: 0.1; VDC_V: 75; TempCo: 100 ppm/C; EIA_Code: E96; U/M: EA
R29 = CRCW060386K6FKEA: RES, 86.6k ohm, 1%, 0.1W, 0603; Manufacturer: Vishay-Dale; CompType: Resistor; Res_ohm: 86600; Value_Code: 86k6; Tolerance_%: 1; Power_W: 0.1; VDC_V: 75; TempCo: 100 ppm/C; EIA_Code: E96; U/M: EA
R31 R32 = CRCW06037K50FKEA: RES, 7.50k ohm, 1%, 0.1W, 0603; Manufacturer: Vishay-Dale; CompType: Resistor; Res_ohm: 7500; Value_Code: 7k50; Tolerance_%: 1; Power_W: 0.1; VDC_V: 75; TempCo: 100 ppm/C; EIA_Code: E96; U/M: EA
R34 = CRCW12061R00FKEA: RES, 1.00 ohm, 1%, 0.25W, 1206; Manufacturer: Vishay-Dale; CompType: Resistor; Res_ohm: 1; Value_Code: 1R00; Power_W: 0.25; VDC_V: 200; TempCo: 100 ppm/C; EIA_Code: E96; U/M: EA
R36 = CRCW1206698KFKEA: RES, 698k ohm, 1%, 0.25W, 1206; Manufacturer: Vishay-Dale; CompType: Resistor; Res_ohm: 698000; Tolerance_%: 1; Power_W: 0.25; VDC_V: 200; TempCo: 100 ppm/C; EIA_Code: E96; U/M: EA
R37 R40 = CRCW1206715KFKEA: RES, 715k ohm, 1%, 0.25W, 1206; Manufacturer: Vishay-Dale; CompType: Resistor; Res_ohm: 715000; Tolerance_%: 1; Power_W: 0.25; VDC_V: 200; TempCo: 100 ppm/C; EIA_Code: E96; U/M: EA
R39 = CRCW06038K25FKEA: RES, 8.25k ohm, 1%, 0.1W, 0603; Manufacturer: Vishay-Dale; CompType: Resistor; Res_ohm: 8250; Value_Code: 8k25; Tolerance_%: 1; Power_W: 0.1; VDC_V: 75; TempCo: 100 ppm/C; EIA_Code: E96; U/M: EA
R42 = CRCW0603909KFKEA: RES, 909k ohm, 1%, 0.1W, 0603; Manufacturer: Vishay-Dale; CompType: Resistor; Res_ohm: 909000; Tolerance_%: 1; Power_W: 0.1; VDC_V: 75; TempCo: 100 ppm/C; EIA_Code: E96; U/M: EA
R43 = CRCW06036K81FKEA: RES, 6.81k ohm, 1%, 0.1W, 0603; Manufacturer: Vishay-Dale; CompType: Resistor; Res_ohm: 6810; Value_Code: 6k81; Tolerance_%: 1; Power_W: 0.1; VDC_V: 75; TempCo: 100 ppm/C; EIA_Code: E96; U/M: EA
R44-R47 = CRCW1206750KFKEA: RES, 750k ohm, 1%, 0.25W, 1206; Manufacturer: Vishay-Dale; CompType: Resistor; Res_ohm: 750000; Tolerance_%: 1; Power_W: 0.25; VDC_V: 200; TempCo: 100 ppm/C; EIA_Code: E96; U/M: EA
RF1 = EMC2-22RKI: RES, 22 ohm, 10%, 2W, Fusible, TH; Manufacturer: TT Electronics/IRC; SymbolCreator: a0412235; CompType: Fusible Resistor; Res_ohm: 22; Value_Code: 22R0; Tolerance_%: 10; Power_W: 2; VDC_V: 500; TempCo: 100 ppm/C; U/M: EA
RT1 = THERMISTOR-B57364_SERIES: Thermistor, 10 Ohms, ±20%; Manufacturer: Epcos; Area: 80.50 mm
RV1 = VARISTOR_SIOV-S20K275: Varistor,  Disk, 350V, 1W, TA @ 85C°; Manufacturer: Epcos; Area: 189800; Value: {Value}
T1 = 760871113: Transformer, 1.31mH, SMT; Manufacturer: Wurth Elektronik eiSos; SymbolCreator: x0208326; DCR_Ohm: 3; LeakageL: 40uH; U/M: EA
T2 = PA3000NL: Transformer, 4 H, TH; Manufacturer: Pulse Engineering; SymbolCreator: Altium; DCR_Ohm: 70; U/M: EA
TP1 TP2 TP11 TP12 TP15 = 5008: Test Point, Compact, Orange, TH; Manufacturer: Keystone; CompType: Test Point Loop; U/M: EA
TP3 = 5005: Test Point, Compact, Red, TH; Manufacturer: Keystone; CompType: Test Point Loop; U/M: EA
TP4 TP5 TP7 = 5122: Test Point, Compact, Blue, TH; Manufacturer: Keystone; CompType: Test Point Loop; U/M: EA
TP6 = 5006: Test Point, Compact, Black, TH; Manufacturer: Keystone; CompType: Test Point Loop; U/M: EA
TP8 = 5000: Test Point, Miniature, Red, TH; Manufacturer: Keystone; CompType: Test Point Loop; U/M: EA
TP9 = 5004: Test Point, Miniature, Yellow, TH; Manufacturer: Keystone; CompType: Test Point Loop; U/M: EA
TP10 = 5001: Test Point, Miniature, Black, TH; Manufacturer: Keystone; CompType: Test Point Loop; U/M: EA
U1 U2 = UCC27517DBV: IC, 4A Single Channel High-Speed Low-Side Gate Drivers; Manufacturer: TI; Alternate Manufacturer: None; Area: 23360
U3 = UCC28180D: 8-PIN CONTINUOUS CONDUCTION MODE (CCM) PFC CONTROLLER, D0008A; Alternate Manufacturer: None; Manufacturer: Texas Instruments; SymbolCreator: a0411947; CompType: IC; U/M: EA
U4 U5 U8 = FOD817DS: Optocoupler, 5kV RMS, SMT; Manufacturer: Fairchild Semiconductor; U/M: EA
U6 = LM5023MM: IC, AC-DC Quasi-Resonant Current Mode PWM Controller; Manufacturer: Texas Instruments; Alternate Manufacturer: None; Area: 39750
U7 U9 = LMV431AIMF: Low-Voltage (1.24V) Adjustable Precision Shunt Regulator, 3-pin SOT-23; Manufacturer: Texas Instruments; PackageTopMarking: RLA*XTT; PowerWise: N; CompType: MiscPower

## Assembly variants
001: not fitted FID1 FID2 FID3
